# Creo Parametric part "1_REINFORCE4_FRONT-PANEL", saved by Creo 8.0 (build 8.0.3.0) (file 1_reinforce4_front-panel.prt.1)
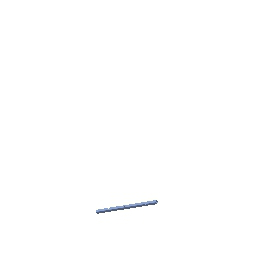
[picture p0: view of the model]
Units: millimeter Newton Second (mmNs); MM, TONNE, SECS

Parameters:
  SMT_DFLT_BEND_REL_LENGTH_TYPE = "Through All"

Other parameters: SMT_THICKNESS, SMT_PART_BEND_ALLOWANCE_FACTOR, SMT_DFLT_BEND_RADIUS, SMT_DFLT_BEND_ANGLE, SMT_DFLT_CRNR_REL_WIDTH, SMT_DFLT_CRNR_REL_DEPTH, SMT_DFLT_BEND_REL_WIDTH, SMT_DFLT_BEND_REL_DEPTH, SMT_DFLT_BEND_REL_LENGTH, SMT_DFLT_BEND_REL_ANGLE, SMT_GAP, SMT_DFLT_EDGE_TREA_WIDTH, SMT_DFLT_MITER_CUT_WIDTH, SMT_DFLT_MITER_CUT_OFFSET

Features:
  1. datum plane "DTM1"
  2. datum plane "DTM2"
  3. datum plane "DTM3"
  4. coordinate system
  5. datum plane "DTM4"
  6. protrusion
  7. round
  8. cut
  9. cut

Other named items: CS0

Layers: 0_ALL_AXIS, 0_ALL_CSYS, 0_ALL_CURVES, 0_ALL_PLANES, 0_ALL_POINTS, 0_ALL_SURFS, REINFORCE4_FRONT-PANEL

Surfaces: 24 plane, 13 cylinder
